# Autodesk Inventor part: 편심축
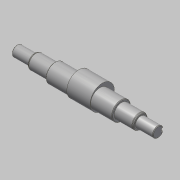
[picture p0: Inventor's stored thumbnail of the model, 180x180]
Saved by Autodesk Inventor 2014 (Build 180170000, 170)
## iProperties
Created: 2015-10
Part Number: 편심축
Document SubType Name: Modeling
Designer: mdu
Density: 7.86 g/cm^3
Material: 강철, 연강
Mass: 1267.06 g
Surface Area: 239.297 cm^2
Volume: 161.203 cm^3
Appearance: Steel
Author: mdu
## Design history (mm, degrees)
sketch "스케치1"
  geometry: L1 (-20.5, -41.331)-(-20.5, 32.669) reference; L2 (7.5, -30.031)-(7.5, 21.369) reference; L3 (135.5, -30.331)-(135.5, 21.669) reference; L4 (121.5, 21.369)-(121.5, -30.031) reference; L5 (184.5, -4.331)-(-57.5, -4.331); L6 (184.5, -4.331)-(184.5, 4.669); L7 (154.5, 8.169)-(121.5, 8.169); L8 (121.5, 8.169)-(121.5, 11.669); L9 (121.5, 11.669)-(7.5, 11.669); L10 (7.5, 11.669)-(7.5, 8.169); L11 (7.5, 8.169)-(-27.5, 8.169); L12 (-27.5, 8.169)-(-27.5, 4.669); L13 (-27.5, 4.669)-(-57.5, 4.669); L14 (-57.5, 4.669)-(-57.5, -4.331); L15 (154.5, 8.169)-(154.5, 4.669); L16 (154.5, 4.669)-(184.5, 4.669); C1 r 32.5 at (64.5, -4.331) reference; 1 further point
  constraints: 24 end point, 8 perpendicular, 5 point on line, 3 parallel, 2 collinear
  dimensions: "d1" = 25 diameter of L11 L5; "d2" = 32 diameter of L9 L5; "d3" = 18 diameter of L13 L5; "d4" = 35 distance of L10.end L11.end; "d5" = 30 distance of L12.end L13.end; "d15" = 33 distance of L7.start L7.end; "d26" = 30 distance of L15.end L6.end
revolve "회전1" sketch "스케치1" stored, may be unused: angle "d6" = 90 deg
node "작업 평면1"
sketch "스케치2"
  geometry: C1 r 16 at (0, 0) reference; C2 r 20.75 at (0, 4)
  constraints: 1 centre point, 1 vertical alignment
  dimensions: "d34" = 4 distance of C2.centre C1.centre; "d35" = 41.5 diameter of C2
extrude "돌출1" join sketch "스케치2" stored distance "d9" = 40; taper "d10" = 0 deg
chamfer "모따기1" distance "d11" = 1; stored, may be unused: second distance "d12" = 2, angle "d13" = 45 deg
node "작업 평면2"
sketch "스케치3"
  geometry: L1 (-15, -8)-(-15, 8) reference; L2 (-15, 3)-(0, 3); L3 (0, -3)-(-15, -3); A1 r 3 centre (0, 0) between (0, -3) and (0, 3); 2 further points
  constraints: 4 end point, 2 perpendicular, 2 point on circle, 2 point on line, 2 tangent, 1 centre point, 1 horizontal alignment, 1 midpoint
  dimensions: "d16" = 18 dimension on A1 L1; "d17" = 6 distance between parallel lines of L3 L2
extrude "돌출2" cut sketch "스케치3" distance "d18" = 3.5; taper "d19" = 0 deg
node "작업 평면3"
chamfer "모따기2" distance "d36" = 2.2; stored, may be unused: second distance "d37" = 2, angle "d38" = 30 deg
chamfer "모따기3" distance "d39" = 2.2; stored, may be unused: second distance "d40" = 2, angle "d41" = 30 deg
fillet "모깎기1" dims "d42" = 1, "d43" = 2
fillet "모깎기2" dims "d44" = 1, "d45" = 2
node "솔리드1"
mirror "대칭1"
node "참조1"
node "참조2"
node "참조3"
node "참조4"
node "참조5"
other parameters: "d30" = 35
